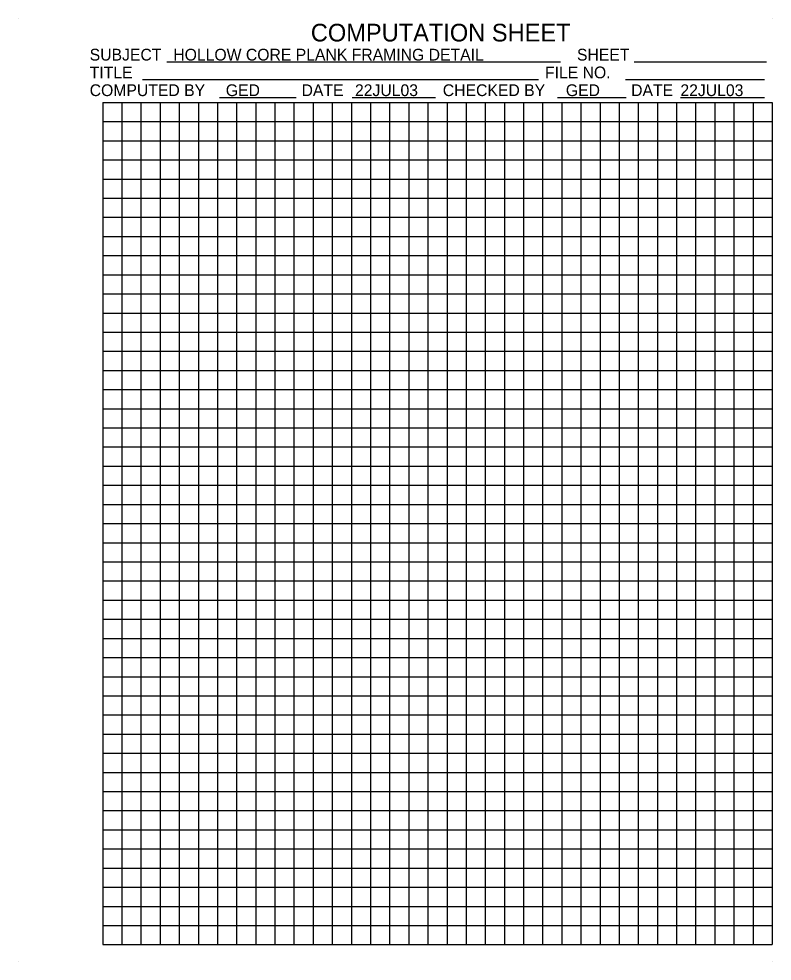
# Model space of a CAD drawing. Extents: x 0 to 0.667, y 0 to 0.833.
import ezdxf

# ---------------------------------------------------------------- set-up
doc = ezdxf.new("R2010")
doc.units = 0
doc.layers.add('S-ANNO-NPLT', color=7, linetype='Continuous')
doc.layers.add('S-ANNO-TEXT', color=7, linetype='Continuous')

msp = doc.modelspace()

# ---------------------------------------------------------------- linework, layer by layer
at = {"layer": 'S-ANNO-NPLT'}
for p, q in [((0.07423, 0.75939), (0.66667, 0.75939)), ((0.07423, 0.75939), (0.07423, 0.01461)), ((0.09116, 0.75939), (0.09116, 0.01461)), ((0.10808, 0.75939), (0.10808, 0.01461)), ((0.12501, 0.75939), (0.12501, 0.01461)), ((0.14194, 0.75939), (0.14194, 0.01461)), ((0.15886, 0.75939), (0.15886, 0.01461)), ((0.17579, 0.75939), (0.17579, 0.01461)), ((0.19272, 0.75939), (0.19272, 0.01461)), ((0.20965, 0.75939), (0.20965, 0.01461)), ((0.22656, 0.75939), (0.22656, 0.01461)), ((0.24349, 0.75939), (0.24349, 0.01461)), ((0.26042, 0.75939), (0.26042, 0.01461)), ((0.27734, 0.75939), (0.27734, 0.01461)), ((0.29427, 0.75939), (0.29427, 0.01461)), ((0.3112, 0.75939), (0.3112, 0.01461)), ((0.32813, 0.75939), (0.32813, 0.01461)), ((0.34505, 0.75939), (0.34505, 0.01461)), ((0.36198, 0.75939), (0.36198, 0.01461)), ((0.37891, 0.75939), (0.37891, 0.01461)), ((0.39583, 0.75939), (0.39583, 0.01461)), ((0.41276, 0.75939), (0.41276, 0.01461)), ((0.42969, 0.75939), (0.42969, 0.01461)), ((0.44661, 0.75939), (0.44661, 0.01461)), ((0.46354, 0.75939), (0.46354, 0.01461)), ((0.48047, 0.75939), (0.48047, 0.01461)), ((0.4974, 0.75939), (0.4974, 0.01461)), ((0.51432, 0.75939), (0.51432, 0.01461)), ((0.53125, 0.75939), (0.53125, 0.01461)), ((0.54818, 0.75939), (0.54818, 0.01461)), ((0.5651, 0.75939), (0.5651, 0.01461)), ((0.58203, 0.75939), (0.58203, 0.01461)), ((0.59896, 0.75939), (0.59896, 0.01461)), ((0.61589, 0.75939), (0.61589, 0.01461)), ((0.63281, 0.75939), (0.63281, 0.01461)), ((0.64974, 0.75939), (0.64974, 0.01461)), ((0.66667, 0.75939), (0.66667, 0.0146)), ((0.07423, 0.74246), (0.66667, 0.74246)), ((0.07423, 0.72553), (0.66667, 0.72553)), ((0.07423, 0.7086), (0.66667, 0.7086)), ((0.07423, 0.69168), (0.66667, 0.69168)), ((0.07423, 0.67475), (0.66667, 0.67475)), ((0.07423, 0.65782), (0.66667, 0.65782)), ((0.07423, 0.6409), (0.66667, 0.6409)), ((0.07423, 0.62397), (0.66667, 0.62397)), ((0.07423, 0.60704), (0.66667, 0.60704)), ((0.07423, 0.59011), (0.66667, 0.59011)), ((0.07423, 0.57319), (0.66667, 0.57319)), ((0.07423, 0.55626), (0.66667, 0.55626)), ((0.07423, 0.53933), (0.66667, 0.53933)), ((0.07423, 0.52241), (0.66667, 0.52241)), ((0.07423, 0.50548), (0.66667, 0.50548)), ((0.07423, 0.48855), (0.66667, 0.48855)), ((0.07423, 0.47163), (0.66667, 0.47163)), ((0.07423, 0.4547), (0.66667, 0.4547)), ((0.07423, 0.43777), (0.66667, 0.43777)), ((0.07423, 0.42084), (0.66667, 0.42084)), ((0.07423, 0.40392), (0.66667, 0.40392)), ((0.07423, 0.387), (0.66667, 0.387)), ((0.07423, 0.37007), (0.66667, 0.37007)), ((0.07423, 0.35315), (0.66667, 0.35315)), ((0.07423, 0.33622), (0.66667, 0.33622)), ((0.07423, 0.31929), (0.66667, 0.31929)), ((0.07423, 0.30236), (0.66667, 0.30236)), ((0.07423, 0.28544), (0.66667, 0.28544)), ((0.07423, 0.26851), (0.66667, 0.26851)), ((0.07423, 0.25158), (0.66667, 0.25158)), ((0.07423, 0.23466), (0.66667, 0.23466)), ((0.07423, 0.21773), (0.66667, 0.21773)), ((0.07423, 0.2008), (0.66667, 0.2008)), ((0.07423, 0.18388), (0.66667, 0.18388)), ((0.07423, 0.16695), (0.66667, 0.16695)), ((0.07423, 0.15002), (0.66667, 0.15002)), ((0.07423, 0.13309), (0.66667, 0.13309)), ((0.07423, 0.11617), (0.66667, 0.11617)), ((0.07423, 0.09924), (0.66667, 0.09924)), ((0.07423, 0.08231), (0.66667, 0.08231)), ((0.07423, 0.06539), (0.66667, 0.06539)), ((0.07423, 0.04846), (0.66667, 0.04846)), ((0.07423, 0.03153), (0.66667, 0.03153)), ((0.07423, 0.0146), (0.66667, 0.0146))]:
    msp.add_line(p, q, dxfattribs=at)
at = {"layer": 'S-ANNO-TEXT'}
for p, q in [((0, 0.83333), (0, 0.83333)), ((0.66667, 0.83333), (0.66667, 0.83333)), ((0, 0), (0, 0)), ((0.66667, 0), (0.66667, 0))]:
    msp.add_line(p, q, dxfattribs=at)
for points in [[(0.13105, 0.79529), (0.47921, 0.79529)], [(0.54446, 0.79529), (0.66151, 0.79529)], [(0.10953, 0.77957), (0.45983, 0.77957)], [(0.53694, 0.77957), (0.65992, 0.77957)], [(0.17769, 0.76386), (0.24535, 0.76386)], [(0.29509, 0.76386), (0.36866, 0.76386)], [(0.47675, 0.76386), (0.5375, 0.76386)], [(0.58545, 0.76386), (0.65992, 0.76386)]]:
    msp.add_lwpolyline(points, dxfattribs=at)

# ---------------------------------------------------------------- texts
for s, height, p in [('COMPUTATION SHEET', 0.015625, (0.2584, 0.81333)), ('SUBJECT', 0.010417, (0.06271, 0.79645)), ('HOLLOW CORE PLANK FRAMING DETAIL', 0.0104167, (0.13669, 0.79645)), ('SHEET', 0.010417, (0.49393, 0.79645)), ('TITLE', 0.010417, (0.06271, 0.78073)), ('FILE NO.', 0.010417, (0.46561, 0.78073)), ('COMPUTED BY', 0.0104167, (0.06271, 0.76501)), ('GED', 0.010417, (0.18316, 0.76501)), ('DATE', 0.010417, (0.2502, 0.76501)), ('22JUL03', 0.010417, (0.29748, 0.76501)), ('CHECKED BY', 0.010417, (0.3752, 0.76501)), ('GED', 0.010417, (0.48407, 0.76501)), ('DATE', 0.010417, (0.54186, 0.76501)), ('22JUL03', 0.010417, (0.58545, 0.76501))]:
    msp.add_text(s, height=height, dxfattribs=at).set_placement(p)

doc.saveas('drawing.dxf')
